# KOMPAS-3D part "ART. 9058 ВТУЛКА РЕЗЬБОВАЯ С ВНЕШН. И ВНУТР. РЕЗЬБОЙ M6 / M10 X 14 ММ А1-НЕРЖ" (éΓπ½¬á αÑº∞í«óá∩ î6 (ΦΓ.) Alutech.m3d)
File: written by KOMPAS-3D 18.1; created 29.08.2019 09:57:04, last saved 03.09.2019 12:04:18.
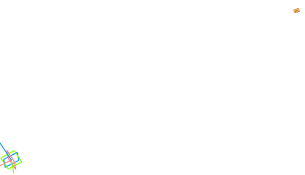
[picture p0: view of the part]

Document properties: Автор: Пользователь Windows; Полное имя файла: D:\Мембранные насосы\Мембранный электропривод\А302-00.00.000 - ASTRA-302 (МЭ200)\3Д ПВХ\Втулка резьбовая М6 (шт.) Alutech.m3d

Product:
- Part/product: ART. 9058 ВТУЛКА РЕЗЬБОВАЯ С ВНЕШН. И ВНУТР. РЕЗЬБОЙ M6 / M10 X 14 ММ А1-НЕРЖ
    Масса: 0.00577673

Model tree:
1. Эскиз:2  (labels: Втулка резьбовая М6 (шт.) Alutech Артикул  408510000 M6I)
2. Элемент выдавливания:1
     Расстояние 1 = 14
3. Условное изображение резьбы:1  (with: Элемент выдавливания:1)  (labels: M6x0.75; cil0_24705-2004 fine)
     Длина резьбы = 14; Шаг резьбы = 0.75; Номинальный диаметр резьбы = 6
4. Подгонка:1  (with: Элемент выдавливания:1)
5. Условное изображение резьбы:2  (with: Элемент выдавливания:1, Подгонка:1)  (labels: M10x1.25; cil0_24705-2004 fine)
     Длина резьбы = 14; Шаг резьбы = 1.25; Номинальный диаметр резьбы = 10
6. Эскиз:3  (with: Элемент выдавливания:1)
7. Элемент выдавливания:2
     Расстояние 2 = 7

Referenced files in D:\Мембранные насосы\Мембранный электропривод\А302-00.00.000 - ASTRA-302 (МЭ200)\3Д ПВХ\: А302-01.12.000 - Крышка.a3d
